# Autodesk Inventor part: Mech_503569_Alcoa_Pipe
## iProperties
Shininess: 64.0
Length Units: 11272
Angle Units: 11279
Time Units: 11290
Mass Units: 11286
Length Display Precision: 3
Angle Display Precision: 2
Compacted: True
Part Number: Mech_503569_Alcoa_Pipe
Document SubType Name: Modeling
Created: 2005-05
Designer: John Blackburn
Manufacturer: Standard
Standards Organization: Custom
Material: Aluminum-6061
Density: 0.0
Volumn: 0.0
Area: 0.0
PropertySet Name: Model Information
Control State: 0
Master: False
Checked Out: False
Author: John Blackburn
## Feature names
1. Extrusion1
